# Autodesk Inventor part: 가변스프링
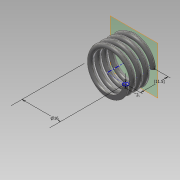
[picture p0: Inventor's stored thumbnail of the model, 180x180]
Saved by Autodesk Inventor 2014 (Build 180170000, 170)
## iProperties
Created: 2015-04
Part Number: 가변스프링
Material: 강철, 탄소
Document SubType Name: Modeling
Designer: Administrator
Density: 7.87 g/cm^3
Appearance: 반연마
Mass: 4.78779 g
Surface Area: 12.524 cm^2
Volume: 0.60836 cm^3
Author: Administrator
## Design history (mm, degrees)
sketch "스케치1"
  geometry: L1 (0, 0)-(8, 0); L2 (8, 0)-(8, 11.5); L3 (8, 11.5)-(0, 11.5); L4 (0, 11.5)-(0, 0); C1 r 1 at (8, 0)
  constraints: 8 end point, 2 parallel, 1 centre point, 1 coincident, 1 horizontal, 1 perpendicular
  dimensions: "d0" = 16 diameter of L2 L4; "d1" = 11.50049 distance between parallel lines of L3 L1 (derived); "d2" = 2 diameter of C1
feature "코일1" pitch "d3" = 10; turns "d5" = 4; dims "d4" = 11.50049 (= d1), "d6" = 0, angle "d7" = 90 deg, angle "d8" = 90 deg, "d9" = 0, "d10" = 0
sketch "스케치2"
  geometry: L1 (-9, 0)-(-7, 0) reference; 1 further point
  constraints: 1 horizontal alignment
extrude "돌출1" cut sketch "스케치2" stored distance "d11" = 10; taper "d12" = 0 deg
node "작업 평면1"
sketch "스케치3"
  geometry: L1 (-7, 0)-(-9, 0) reference; 1 further point
  constraints: 1 horizontal alignment
extrude "돌출2" cut sketch "스케치3" stored distance "d13" = 10; taper "d14" = 0 deg
node "솔리드1"
node "절단 모서리 투영1"
node "절단 모서리 투영2"
